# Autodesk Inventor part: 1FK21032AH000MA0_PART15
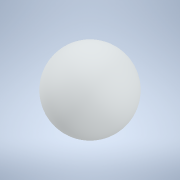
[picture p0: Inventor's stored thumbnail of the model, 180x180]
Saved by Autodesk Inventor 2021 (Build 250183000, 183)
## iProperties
Created: 2025-04
Part Number: 1FK21032AH000MA0_PART15
Material: Generic
Catalog Web Link: www.3dfindit.com
Description: -Servo synchronous motor
Document SubType Name: Modeling
Designer: psAdmin
Mass: 0.113097 g
Surface Area: 1.13097 cm^2
Volume: 0.113097 cm^3
Density: 1 g/cm^3
Appearance: PSOLRGB-212-217-219
Category: PARTsolutions
Title: 1FK21032AH000MA0_PART15
Author: Cadenas PARTsolutions
Comments: Servo synchronous motor
Sending System: PARTsolutions
Preprocessor: ST-DEVELOPER v19.3
PSOL_IDENT_0: {$CADENAS_DATA/23d-libs/siemens_ag/_cat_/45/10/1fk21032ah000ma0.prj},216 {VTYP=3D},{NB=1FK21032AH000
PSOL_IDENT_1: MA0_PART15},{LINA=1FK21032AH000MA0_PART15},{NN=1FK21032AH000MA0_PART15},{NOPRJ=TRUE},{DATE=19.08.202
PSOL_IDENT_2: 5 14:00:35},{GEOMDATE=30.07.2025 02:02:03},{VERSION=},{LINEID=10},{WBVAR=},{WBNUMERIC=}  {NB=1FK2103
PSOL_IDENT_3: 2AH000MA0_PART15},{LINA=1FK21032AH000MA0_PART15},{KT=DUMMY},{PREVIEW=../../../_pool_/14/8e/p_d211_xx
PSOL_IDENT_4: _00426j.png},{DESCSHORT=SIMOTICS S-1FK2 HD, SINAMICS S210 3AC 400V-480V, 0.59 Nm, 4500 rpm},{DESCLON
PSOL_IDENT_5: G=SIMOTICS S-1FK2 HD servo motor M0=0.64 Nm; PN = 0.28 kW at nN=4500 rpm (380-480 V); PN = 0.167 kW
PSOL_IDENT_6: at nN=2500 rpm (200-240 V); degree of protection IP64; cylindrical shaft D14 x 30 mm; absolute encod
PSOL_IDENT_7: er 22-bit + 12-bit multiturn (encoder AM22DQC); with OCC interface; plug size M17, rotatable; SIMOTI
PSOL_IDENT_8: CS S-1FK2 servomotorfor a wide range of uses in industrial environments. SIMOTICS S‑1FK2 servomotors
PSOL_IDENT_9: are compact synchronous motors with a high dynamic performance that set themselves apart as a resul
PSOL_IDENT_10: t of their high power density, degree of protection and overload capability. The motors are availabl
PSOL_IDENT_11: e in two variants: as High Dynamic variant (highest dynamic performance as a result of the low intri
PSOL_IDENT_12: nsic moment of inertia for applications demanding a high dynamic performance with low moved masses)
PSOL_IDENT_13: - and as Compact variant (precise and stable closed-loop control for medium up to large moved masses
PSOL_IDENT_14: as a result of a medium intrinsic moment of inertia). SIMOTICSS‑1FK2 servomotors fully exploit thei
PSOL_IDENT_15: r strengths in a system with the SINAMICSS210 frequency converter and simple connection using the on
PSOL_IDENT_16: e cable connection (OCC). Advantages include the short control and positioning times, fast and preci
PSOL_IDENT_17: se correction of disturbing quantities as well as stable control with a high dynamic performance. Th
PSOL_IDENT_18: e servo motors can be configured to address a wide range of requirements. For example with and witho
PSOL_IDENT_19: ut holding brake, IP64 or IP65 degree of protection, singleturn or multiturn absolute encoders - to
PSOL_IDENT_20: name just a few. Further, the servomotors are available in different shaft heights extending from 20
PSOL_IDENT_21: to 100. A shaft sealing ring is available to achieve an IP65 degree of protection and for subsequen
PSOL_IDENT_22: t mounting at the motor or as spare part. SIMOTICS - the optimum motor for each and every motion con
PSOL_IDENT_23: trol application.},{INTNO=195125335004},{SUPPLIERALTNO=1FK2103-2AH00-0MA0},{MANUID=1FK21032AH000MA0}
PSOL_IDENT_24: ,{MANUNAME=Siemens},{MANUTYPEDESC=SYNCHRONOUS MOTOR 1FK2 HD 0,64 NM},{AAU732=SIMOTICS},{AAO057=S-1FK
PSOL_IDENT_25: 2},{AAU734=SIMOTICS S-1FK2 HD servo motor M0=0.64 Nm; PN = 0.28 kW at nN=4500 rpm (380-480 V); PN =
PSOL_IDENT_26: 0.167 kW at nN=2500 rpm (200-240 V); degree of protection IP64; cylindrical shaft D14 x 30 mm; absol
PSOL_IDENT_27: ute encoder 22-bit + 12-bit multiturn (encoder AM22DQC); with OCC interface; plug size M17, rotatabl
PSOL_IDENT_28: e;},{AAW338=SYNCHRONOUS MOTOR 1FK2 HD 0,64 NM},{AAO742=SIMOTICS},{AAO663=4034106444624},{NOCUPEROU=1
PSOL_IDENT_29: },{PRICEQUANTITY=1},{QUANTITYMIN=1},{QUANTITYINT=1},{CTN=85015100},{COO=RO},{AAO676=1FK2103-2AH00-0M
PSOL_IDENT_30: A0},{AAO677=Siemens AG},{ORDERUNIT=C62},{CONTENTUNIT=C62}
NB: 1FK21032AH000MA0_PART15
NT: Servo synchronous motor
NBSYN: $MANUID._PART15
LINA: 1FK21032AH000MA0_PART15
CATALOG: SIEMENS
PREVIEW: ../../../_pool_/14/8e/p_d211_xx_00426j.png
DESCSHORT: SIMOTICS S-1FK2 HD, SINAMICS S210 3AC 400V-480V, 0.59 Nm, 4500 rpm
DESCLONG: SIMOTICS S-1FK2 HD servo motor M0=0.64 Nm; PN = 0.28 kW at nN=4500 rpm (380-480 V); PN = 0.167 kW at nN=2500 rpm (200-240 V); degree of protection IP64; cylindr
INTNO: 195125335004
SUPPLIERALTNO: 1FK2103-2AH00-0MA0
MANUID: 1FK21032AH000MA0
MANUNAME: Siemens
MANUTYPEDESC: SYNCHRONOUS MOTOR 1FK2 HD 0,64 NM
AAU732: SIMOTICS
AAO057: S-1FK2
AAU734: SIMOTICS S-1FK2 HD servo motor M0=0.64 Nm; PN = 0.28 kW at nN=4500 rpm (380-480 V); PN = 0.167 kW at nN=2500 rpm (200-240 V); degree of protection IP64; cylindr
AAW338: SYNCHRONOUS MOTOR 1FK2 HD 0,64 NM
AAO742: SIMOTICS
AAO663: 4034106444624.0
NOCUPEROU: 1
PRICEQUANTITY: 1
QUANTITYMIN: 1
QUANTITYINT: 1
CTN: 85015100
COO: RO
ARTICLENO: 1FK21032AH000MA0_PART15
BOMINFO: 1FK21032AH000MA0_PART15
CREATOR: CADENAS GmbH
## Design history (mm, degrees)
feature "2025_04_17_15_00_20_0760"
body "Solid1"
